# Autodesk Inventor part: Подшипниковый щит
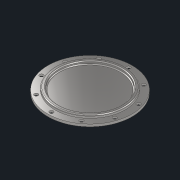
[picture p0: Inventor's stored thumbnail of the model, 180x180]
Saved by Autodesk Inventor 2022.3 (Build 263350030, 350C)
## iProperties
Created: 2022-08
Part Number: Подшипниковый щит
Material: Сталь 40ХНМА
Document SubType Name: Modeling
Designer: Карташов
Density: 7.85 g/cm^3
Appearance: С умеренной полировкой
Author: Карташов
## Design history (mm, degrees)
sketch "Эскиз1"
  geometry: L1 (0, 0)-(0, 34.001); L2 (50, -5)-(90, -5); L3 (90, -5)-(90, 0); L4 (90, 0)-(75, 0); L5 (75, 0)-(75, 4); L6 (73, 6)-(69, 6); L7 (67, 4)-(67, 2); L8 (65, 0)-(0, 0); L9 (50, -5)-(48, -7); L10 (48, -7)-(0, -7); L11 (0, -7)-(0, 0); A1 r 2 centre (65, 2) between (65, 0) and (67, 2); A2 r 2 centre (73, 4) between (75, 4) and (73, 6); A3 r 2 centre (69, 4) between (69, 6) and (67, 4); 4 further points
  constraints: 22 end point, 6 point on circle, 6 tangent, 5 horizontal, 4 point on line, 3 centre point, 3 vertical, 2 midpoint, 2 perpendicular
  dimensions: "d0" = 150 diameter of L5 point (0, 17); "d1" = 180 diameter of L3 L1; "d4" = 5 distance of L2.end L3.end; "d5" = 6 distance between parallel lines of L8 L6; "d6" = 8 distance of point (75, 6) point (67, 6); "d7" = 2 radius of A1; "d21" = 2 horizontal distance of L2.start L9.end; "d22" = 2 horizontal distance of L2.start L9.end; "d23" = 100 diameter of L2.start L1; "d24" = 2 radius of A2; "d25" = 2 radius of A3 (derived); "d26" = 13 distance from line of point (71, 6) L10
revolve "Вращение1" sketch "Эскиз1" stored, may be unused: angle "d9" = 90 deg
sketch "Эскиз2"
  geometry: C1 r 75 at (0, 0) reference; C2 r 90 at (0, 0) reference; 2 further points
  constraints: 1 vertical alignment
  dimensions: "d10" = 82.5 distance of point (0, 0) point (0, -82.5)
  node "Спроецированная петля1"
sketch "Эскиз3"
  geometry: 2 further points
hole "Отверстие1" sketch "Эскиз3" at (0, 82.5) diameter "d11" = 8; stored, may be unused: countersink angle "d15" = 90 deg, drill point angle "d17" = 0 deg; dims "d12" = 6, "d13" = 13, "d14" = 1, "d16" = 22.5
pattern_circular "Круговой массив1" dims angle "d19" = 360 deg
node "Твердое тело1"
